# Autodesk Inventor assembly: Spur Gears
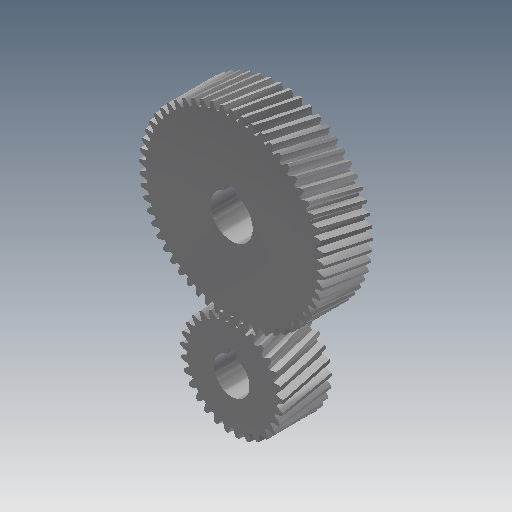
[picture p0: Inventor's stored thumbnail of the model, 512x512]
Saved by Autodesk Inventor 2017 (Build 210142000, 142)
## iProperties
Created: 2019-03
Part Number: Spur Gears
Document SubType Name: Assembly
Designer: user
Categories: <?xml version="1.0" encoding="UTF-16"?> <MemberInstance><Categories><FamilyTemplate/><ParamToTemplateMap><ParamToTemplate><ParamToTemplate CategoryParameter="//
ClientObjectVersion: 1
Author: user
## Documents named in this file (3)
- C:\Users\user\Documents\EIA\Cursos\Diseño asistido por computador\Clase 7 Dynamic simulation\Ensamble reductor de velocidad\Ensamble\Design Accelerator\Spur Gears1.iam
- C:\Users\user\Documents\EIA\Cursos\Diseño asistido por computador\Clase 7 Dynamic simulation\Ensamble reductor de velocidad\Ensamble\Design Accelerator\Spur Gear11.ipt
- C:\Users\user\Documents\EIA\Cursos\Diseño asistido por computador\Clase 7 Dynamic simulation\Ensamble reductor de velocidad\Ensamble\Design Accelerator\Spur Gear21.ipt
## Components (2 placed, 2 different names)
1. Spur Gear1:1 — Rotation:1
2. Spur Gear2:1 — Rotation:1
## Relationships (1: RelateRotation 1)
- Rotation:1 [RelateRotation]: Spur Gear1:1 ↔ Spur Gear2:1
